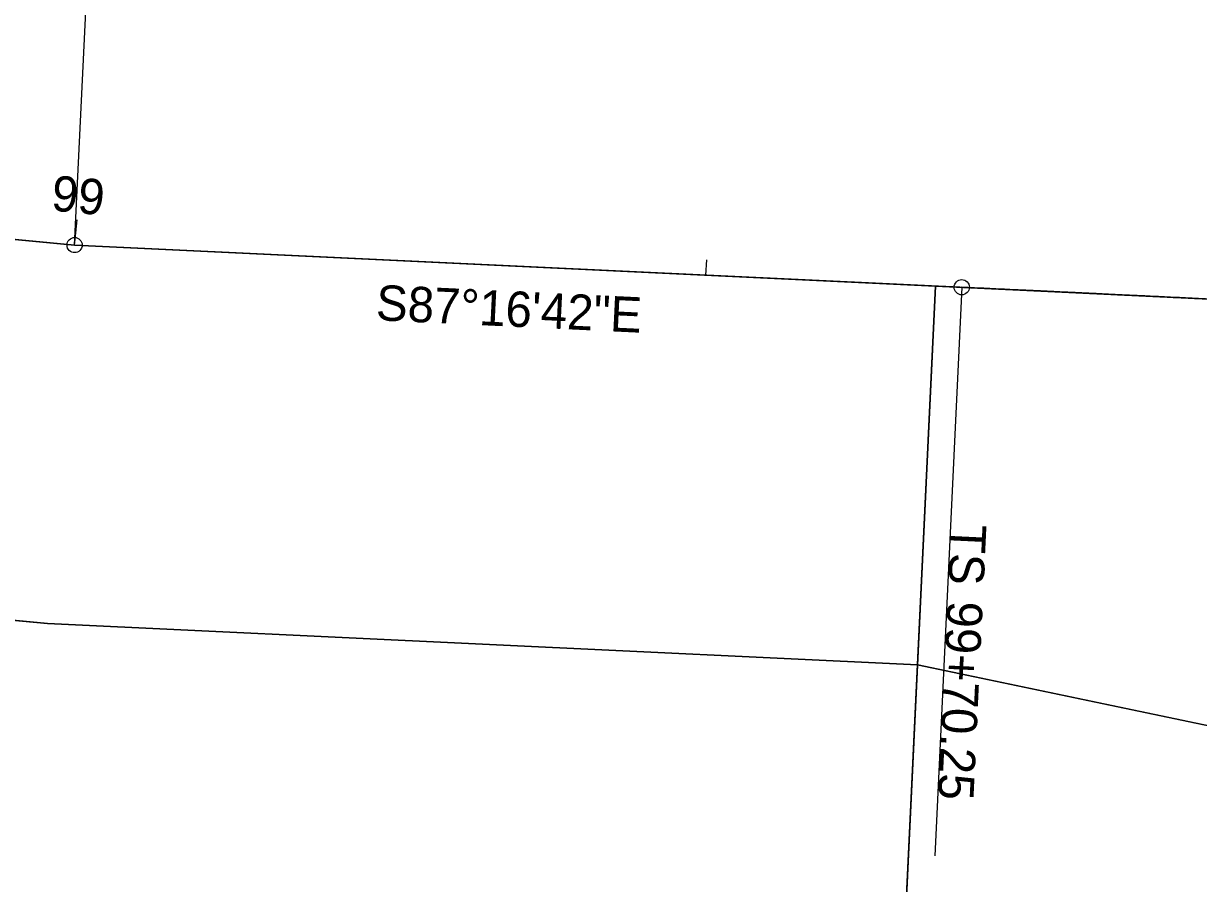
# Model space of a CAD drawing. Extents: x 2318731 to 2320621, y 732958 to 734198.
# Drawn here: x 2319231.8 to 2319324.8, y 733492.7 to 733560.7 of the extents above; entities that cross this region are included whole.
import ezdxf

# ---------------------------------------------------------------- set-up
doc = ezdxf.new("R2010")
doc.units = 0
for name, color, linetype in [('RW_X_CL_100_Bearings', 7, 'Continuous'), ('RW_X_CL_100_Cardinal_Points', 7, 'Continuous'), ('RW_X_CL_100_Stations', 7, 'Continuous'), ('RW_X_CL_500_Bearings', 7, 'Continuous'), ('RW_X_CL_500_Cardinal_Points', 7, 'Continuous'), ('RW_X_CL_500_Stations', 7, 'Continuous'), ('SC_Scratch4', 7, 'Continuous'), ('SC_Scratch5', 7, 'Continuous'), ('V-SURV-IPF', 7, 'Continuous'), ('V-SURV-PARL-LINE', 7, 'Continuous'), ('V-SURV-RWAY', 7, 'Continuous')]:
    doc.layers.add(name, color=color, linetype=linetype)

msp = doc.modelspace()

# ---------------------------------------------------------------- linework, layer by layer
at = {"layer": 'RW_X_CL_100_Cardinal_Points'}
for p, q in [((2319235.879, 733543.147), (2319238.016, 733588.096)), ((2319306.055, 733539.811), (2319303.918, 733494.862))]:
    msp.add_line(p, q, dxfattribs=at)
for centre in [(2319235.879, 733543.147), (2319306.055, 733539.811)]:
    msp.add_circle(centre, 0.6, dxfattribs=at)
at = {"layer": 'RW_X_CL_100_Stations'}
for p, q in [((2319235.879, 733543.147), (2319236.069, 733545.138)), ((2319285.823, 733540.773), (2319285.88, 733541.971))]:
    msp.add_line(p, q, dxfattribs=at)
at = {"layer": 'RW_X_CL_500_Cardinal_Points'}
for p, q in [((2319235.879, 733543.147), (2319238.016, 733588.096)), ((2319306.055, 733539.811), (2319303.918, 733494.862))]:
    msp.add_line(p, q, dxfattribs=at)
for centre in [(2319235.879, 733543.147), (2319306.055, 733539.811)]:
    msp.add_circle(centre, 0.6, dxfattribs=at)
at = {"layer": 'RW_X_CL_500_Stations'}
msp.add_line((2319235.879, 733543.147), (2319235.993, 733544.341), dxfattribs=at)
at = {"layer": 'SC_Scratch4'}
for points in [[(2319238.014, 733573.079), (2319387.148, 733565.99), (2319438.367, 733857.203), (2319458.709, 733857.406), (2319402.048, 733535.248), (2319235.879, 733543.147), (2319201.733, 733546.397), (2319204.577, 733576.262)], [(2319235.879, 733543.147), (2319303.982, 733539.909), (2319302.558, 733509.943), (2319233.744, 733513.214), (2319127.981, 733523.283), (2319130.824, 733553.148)], [(2319303.982, 733539.909), (2319493.768, 733530.888), (2319490.897, 733470.505), (2319302.558, 733509.943)]]:
    msp.add_lwpolyline(points, close=True, dxfattribs=at)
msp.add_lwpolyline([(2318852.084, 733579.684), (2319235.879, 733543.147), (2319306.055, 733539.811)], dxfattribs=at)
at = {"layer": 'SC_Scratch5'}
for points in [[(2319402.048, 733535.248), (2319235.879, 733543.147), (2319201.733, 733546.397), (2319231.115, 733855.029), (2319458.709, 733857.406)], [(2319235.879, 733543.147), (2319303.982, 733539.909), (2319288.313, 733210.282), (2319212.394, 733213.89), (2319099.549, 733224.633), (2319130.824, 733553.148)]]:
    msp.add_lwpolyline(points, close=True, dxfattribs=at)
for points in [[(2319493.525, 733525.78), (2319478.099, 733201.26), (2319288.313, 733210.282), (2319303.982, 733539.909), (2319306.055, 733539.811)], [(2319306.055, 733539.811), (2319493.768, 733530.888), (2319493.525, 733525.78)]]:
    msp.add_lwpolyline(points, dxfattribs=at)
for points, degree in [([(2319306.055, 733539.811), (2319312.298, 733539.514), (2319318.541, 733539.217), (2319324.783, 733538.915)], 2), ([(2319324.783, 733538.915), (2319318.541, 733539.217), (2319312.298, 733539.514), (2319306.055, 733539.811)], 2), ([(2319324.783, 733538.915), (2319331.026, 733538.614), (2319349.753, 733537.693), (2319368.476, 733536.68), (2319380.953, 733535.923)], 3)]:
    msp.add_open_spline(points, degree=degree, dxfattribs=at)
at = {"layer": 'V-SURV-IPF'}
for p, q in [((2319288.313, 733210.282), (2319303.982, 733539.909)), ((2319306.055, 733539.811), (2319793.429, 733516.643))]:
    msp.add_line(p, q, dxfattribs=at)
at = {"layer": 'V-SURV-PARL-LINE'}
for p, q in [((2318879.106, 733546.976), (2319233.744, 733513.214)), ((2319233.744, 733513.214), (2319302.558, 733509.943)), ((2319302.558, 733509.943), (2319715.904, 733423.39))]:
    msp.add_line(p, q, dxfattribs=at)
at = {"layer": 'V-SURV-RWAY'}
for p, q in [((2318852.084, 733579.684), (2319235.879, 733543.147)), ((2319235.879, 733543.147), (2319306.055, 733539.811))]:
    msp.add_line(p, q, dxfattribs=at)
msp.add_open_spline([(2319306.055, 733539.811), (2319312.297, 733539.514), (2319324.783, 733538.921), (2319349.753, 733537.693), (2319380.958, 733536.005), (2319412.139, 733533.908), (2319437.055, 733531.864), (2319449.501, 733530.699), (2319455.72, 733530.076)], degree=3, dxfattribs=at)

# ---------------------------------------------------------------- texts
at = {"layer": 'RW_X_CL_100_Bearings'}
msp.add_text('S87°16\'42"E', height=2.8, rotation=357.27847, dxfattribs=at).set_placement((2319259.678, 733537.21))
at = {"layer": 'RW_X_CL_100_Cardinal_Points'}
for s, p in [('TS', (2319305.213, 733521.114)), ('99+70.25', (2319304.924, 733515.034))]:
    msp.add_text(s, height=2.8, rotation=267.27847, dxfattribs=at).set_placement(p)
at = {"layer": 'RW_X_CL_100_Stations'}
msp.add_text('99', height=2.8, rotation=354.5618, dxfattribs=at).set_placement((2319233.965, 733545.887))
at = {"layer": 'RW_X_CL_500_Bearings'}
msp.add_text('S87°16\'42"E', height=2.8, rotation=357.27847, dxfattribs=at).set_placement((2319259.678, 733537.21))
at = {"layer": 'RW_X_CL_500_Cardinal_Points'}
for s, p in [('TS', (2319305.213, 733521.114)), ('99+70.25', (2319304.924, 733515.034))]:
    msp.add_text(s, height=2.8, rotation=267.27847, dxfattribs=at).set_placement(p)

doc.saveas('drawing.dxf')
